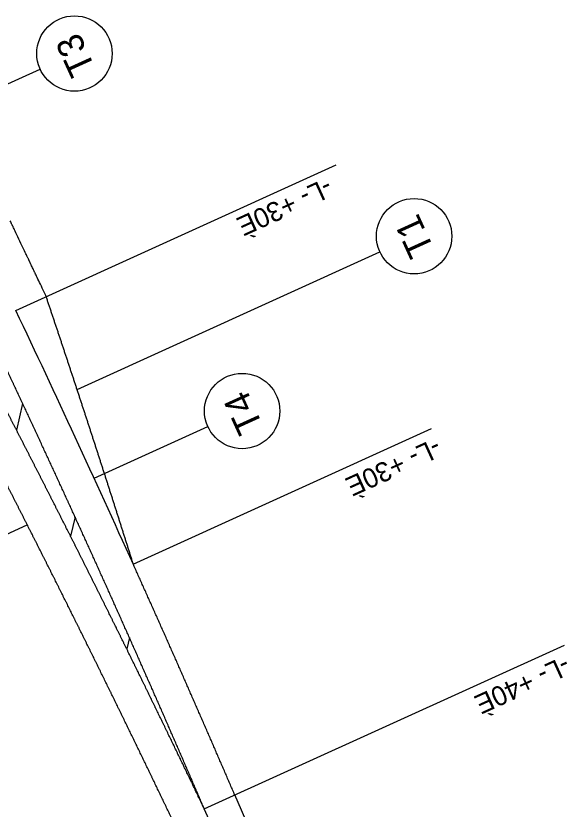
# Model space of a CAD drawing. Extents: x 1657109 to 2100937, y 684916 to 883211.
# Drawn here: x 2097963.2 to 2098160.7, y 685227.5 to 685511.8 of the extents above; entities that cross this region are included whole.
import ezdxf

# ---------------------------------------------------------------- set-up
doc = ezdxf.new("R2010")
doc.units = 0
for name, color, linetype in [('Old_Level_12', 7, 'Continuous'), ('Prop CMT Pvmt Gravel', 7, 'Continuous'), ('Prop Conc 2ft 6in Curb and Gutter', 7, 'Continuous'), ('Prop Guardrail Anchor Unit CELL', 7, 'Continuous'), ('Scratch_Level_1', 7, 'Continuous')]:
    doc.layers.add(name, color=color, linetype=linetype)

msp = doc.modelspace()

# ---------------------------------------------------------------- linework, layer by layer
at = {"layer": 'Old_Level_12'}
for p, q in [((2097965.58, 685372.9), (2097963.4, 685363.32)), ((2097984.37, 685332.2), (2097982.79, 685325.24)), ((2098003.84, 685289), (2098002.9, 685284.87))]:
    msp.add_line(p, q, dxfattribs=at)
at = {"layer": 'Prop CMT Pvmt Gravel'}
for p, q in [((2097931.15, 685474.17), (2097971.87, 685492.7)), ((2097963.18, 685406.16), (2098077.9, 685458.36)), ((2097985.12, 685377.86), (2098093.59, 685427.22)), ((2097991.24, 685346.03), (2098031.96, 685364.56)), ((2098005.22, 685315.27), (2098112.1, 685363.91)), ((2097887.48, 685292.79), (2097967.26, 685329.36)), ((2098030.69, 685227.56), (2098159.71, 685286.27))]:
    msp.add_line(p, q, dxfattribs=at)
for centre in [(2097984.16, 685498.29), (2098105.88, 685432.81), (2098044.25, 685370.15)]:
    msp.add_circle(centre, 13.5, dxfattribs=at)
at = {"layer": 'Prop Conc 2ft 6in Curb and Gutter'}
msp.add_arc((2093433.96, 683256.07), 5013.66, 24.24805, 25.39445, dxfattribs=at)
at = {"layer": 'Prop Guardrail Anchor Unit CELL'}
msp.add_line((2098097.63, 685104.2), (2098041.61, 685232.53), dxfattribs=at)
msp.add_open_spline([(2097973.92, 685411.52), (2097973.6, 685412.19), (2097972.63, 685414.24), (2097971.32, 685416.98), (2097970.33, 685419.06), (2097969.84, 685420.1), (2097969.67, 685420.44), (2097969.34, 685421.13), (2097969.01, 685421.83), (2097968.64, 685422.6), (2097968.43, 685423.06), (2097968.37, 685423.16), (2097968.35, 685423.21), (2097968.34, 685423.23), (2097968.31, 685423.29), (2097968.21, 685423.51), (2097968.11, 685423.72), (2097967.94, 685424.07), (2097967.86, 685424.24), (2097967.7, 685424.59), (2097967.61, 685424.76), (2097967.37, 685425.27), (2097967.2, 685425.62), (2097966.38, 685427.34), (2097965.07, 685430.1), (2097963.43, 685433.55), (2097962.41, 685435.7), (2097962.04, 685436.48), (2097961.96, 685436.65), (2097961.92, 685436.74), (2097961.8, 685437), (2097961.55, 685437.51), (2097961.31, 685438.03), (2097961.14, 685438.38)], degree=3, dxfattribs=at)
for points in [[(2097989.86, 685363.37), (2097989.65, 685364.02), (2097989.44, 685364.67), (2097989.22, 685365.32), (2097989.01, 685365.97), (2097988.8, 685366.62), (2097988.59, 685367.28), (2097988.37, 685367.93), (2097988.16, 685368.58), (2097987.95, 685369.23), (2097987.74, 685369.88), (2097987.52, 685370.53), (2097987.31, 685371.18), (2097987.1, 685371.83), (2097986.88, 685372.49), (2097986.67, 685373.14), (2097986.46, 685373.79), (2097986.24, 685374.44), (2097986.03, 685375.09), (2097985.82, 685375.74), (2097985.6, 685376.39), (2097985.39, 685377.04), (2097985.17, 685377.69), (2097984.96, 685378.35), (2097984.75, 685379), (2097984.53, 685379.65), (2097984.32, 685380.3), (2097984.1, 685380.95), (2097983.89, 685381.6), (2097983.67, 685382.25), (2097983.46, 685382.9), (2097983.24, 685383.55), (2097983.03, 685384.2), (2097982.81, 685384.85), (2097982.6, 685385.51), (2097982.38, 685386.16), (2097982.17, 685386.81), (2097981.95, 685387.46), (2097981.74, 685388.11), (2097981.52, 685388.76), (2097981.31, 685389.41), (2097981.09, 685390.06), (2097980.88, 685390.71), (2097980.66, 685391.36), (2097980.44, 685392.01), (2097980.23, 685392.66), (2097980.01, 685393.31), (2097979.79, 685393.96), (2097979.58, 685394.62), (2097979.36, 685395.27), (2097979.14, 685395.92), (2097978.93, 685396.57), (2097978.71, 685397.22), (2097978.49, 685397.87), (2097978.28, 685398.52), (2097978.06, 685399.17), (2097977.84, 685399.82), (2097977.63, 685400.47), (2097977.41, 685401.12), (2097977.19, 685401.77), (2097976.97, 685402.42), (2097976.76, 685403.07), (2097976.54, 685403.72), (2097976.32, 685404.37), (2097976.1, 685405.02), (2097975.88, 685405.67), (2097975.67, 685406.32), (2097975.45, 685406.97), (2097975.23, 685407.62), (2097975.01, 685408.27), (2097974.79, 685408.92), (2097974.57, 685409.57), (2097974.36, 685410.22), (2097973.92, 685411.52)], [(2098005.29, 685315.12), (2098005.09, 685315.77), (2098004.88, 685316.42), (2098004.67, 685317.07), (2098004.47, 685317.73), (2098004.26, 685318.38), (2098004.06, 685319.03), (2098003.85, 685319.68), (2098003.65, 685320.34), (2098003.44, 685320.99), (2098003.24, 685321.64), (2098003.03, 685322.29), (2098002.82, 685322.95), (2098002.62, 685323.6), (2098002.41, 685324.25), (2098002.2, 685324.9), (2098002, 685325.56), (2098001.79, 685326.21), (2098001.58, 685326.86), (2098001.38, 685327.51), (2098001.17, 685328.17), (2098000.96, 685328.82), (2098000.76, 685329.47), (2098000.55, 685330.12), (2098000.34, 685330.78), (2098000.14, 685331.43), (2097999.93, 685332.08), (2097999.72, 685332.73), (2097999.51, 685333.38), (2097999.3, 685334.04), (2097999.1, 685334.69), (2097998.89, 685335.34), (2097998.68, 685335.99), (2097998.47, 685336.65), (2097998.26, 685337.3), (2097998.06, 685337.95), (2097997.85, 685338.6), (2097997.64, 685339.25), (2097997.43, 685339.91), (2097997.22, 685340.56), (2097997.01, 685341.21), (2097996.8, 685341.86), (2097996.6, 685342.51), (2097996.39, 685343.17), (2097996.18, 685343.82), (2097995.97, 685344.47), (2097995.76, 685345.12), (2097995.55, 685345.77), (2097995.34, 685346.42), (2097995.13, 685347.08), (2097994.92, 685347.73), (2097994.71, 685348.38), (2097994.5, 685349.03), (2097994.29, 685349.68), (2097994.08, 685350.34), (2097993.87, 685350.99), (2097993.66, 685351.64), (2097993.45, 685352.29), (2097993.24, 685352.94), (2097993.03, 685353.59), (2097992.82, 685354.25), (2097992.61, 685354.9), (2097992.4, 685355.55), (2097992.19, 685356.2), (2097991.98, 685356.85), (2097991.76, 685357.5), (2097991.55, 685358.16), (2097991.34, 685358.81), (2097991.13, 685359.46), (2097990.92, 685360.11), (2097990.71, 685360.76), (2097990.5, 685361.41), (2097990.28, 685362.06), (2097990.07, 685362.72), (2097989.86, 685363.37)], [(2097987.77, 685288.41), (2097987.33, 685289.29), (2097986.9, 685290.18), (2097986.46, 685291.06), (2097986.02, 685291.95), (2097985.58, 685292.84), (2097985.14, 685293.72), (2097984.7, 685294.61), (2097984.26, 685295.49), (2097983.82, 685296.38), (2097983.38, 685297.26), (2097982.94, 685298.15), (2097982.5, 685299.03), (2097982.06, 685299.92), (2097981.62, 685300.8), (2097981.18, 685301.69), (2097980.73, 685302.57), (2097980.29, 685303.45), (2097979.85, 685304.34), (2097979.41, 685305.22), (2097978.97, 685306.11), (2097978.53, 685306.99), (2097978.08, 685307.88), (2097977.64, 685308.76), (2097977.2, 685309.64), (2097976.76, 685310.53), (2097976.31, 685311.41), (2097975.87, 685312.29), (2097975.43, 685313.18), (2097974.98, 685314.06), (2097974.54, 685314.94), (2097974.1, 685315.83), (2097973.65, 685316.71), (2097973.21, 685317.59), (2097972.76, 685318.48), (2097972.32, 685319.36), (2097971.87, 685320.24), (2097971.43, 685321.12), (2097970.98, 685322.01), (2097970.54, 685322.89), (2097970.09, 685323.77), (2097969.65, 685324.65), (2097969.2, 685325.54), (2097968.76, 685326.42), (2097968.31, 685327.3), (2097967.86, 685328.18), (2097967.42, 685329.06), (2097966.97, 685329.94), (2097966.52, 685330.83), (2097966.08, 685331.71), (2097965.63, 685332.59), (2097965.18, 685333.47), (2097964.74, 685334.35), (2097964.29, 685335.23), (2097963.84, 685336.11), (2097963.39, 685336.99), (2097962.94, 685337.88), (2097962.5, 685338.76), (2097962.05, 685339.64), (2097961.6, 685340.52), (2097961.15, 685341.4), (2097960.7, 685342.28), (2097960.25, 685343.16), (2097959.8, 685344.04), (2097959.35, 685344.92), (2097958.9, 685345.8), (2097958.45, 685346.68), (2097958, 685347.56), (2097957.55, 685348.44), (2097957.1, 685349.32), (2097956.65, 685350.2), (2097956.2, 685351.08), (2097955.75, 685351.96), (2097955.3, 685352.84), (2097954.85, 685353.72)], [(2098012.13, 685299.86), (2098011.72, 685300.77), (2098011.32, 685301.68), (2098010.91, 685302.59), (2098010.51, 685303.49), (2098010.1, 685304.4), (2098009.7, 685305.31), (2098009.29, 685306.22), (2098008.88, 685307.12), (2098008.48, 685308.03), (2098008.07, 685308.94), (2098007.66, 685309.84), (2098007.26, 685310.75), (2098006.85, 685311.66), (2098006.44, 685312.56), (2098006.03, 685313.47), (2098005.62, 685314.38), (2098005.29, 685315.12)], [(2098041.61, 685232.53), (2098041.22, 685233.44), (2098040.83, 685234.35), (2098040.43, 685235.26), (2098040.04, 685236.17), (2098039.65, 685237.08), (2098039.26, 685237.99), (2098038.86, 685238.9), (2098038.47, 685239.81), (2098038.08, 685240.72), (2098037.69, 685241.63), (2098037.29, 685242.54), (2098036.9, 685243.45), (2098036.5, 685244.36), (2098036.11, 685245.28), (2098035.72, 685246.19), (2098035.32, 685247.1), (2098034.93, 685248.01), (2098034.53, 685248.92), (2098034.14, 685249.84), (2098033.74, 685250.75), (2098033.35, 685251.66), (2098032.95, 685252.57), (2098032.56, 685253.48), (2098032.16, 685254.39), (2098031.76, 685255.3), (2098031.37, 685256.22), (2098030.97, 685257.13), (2098030.57, 685258.04), (2098030.18, 685258.95), (2098029.78, 685259.86), (2098029.38, 685260.77), (2098028.99, 685261.68), (2098028.59, 685262.59), (2098028.19, 685263.5), (2098027.79, 685264.41), (2098027.39, 685265.32), (2098027, 685266.23), (2098026.6, 685267.14), (2098026.2, 685268.05), (2098025.8, 685268.96), (2098025.4, 685269.87), (2098025, 685270.78), (2098024.6, 685271.69), (2098024.2, 685272.6), (2098023.8, 685273.51), (2098023.4, 685274.42), (2098023, 685275.33), (2098022.6, 685276.24), (2098022.2, 685277.15), (2098021.8, 685278.06), (2098021.4, 685278.97), (2098021, 685279.88), (2098020.6, 685280.79), (2098020.2, 685281.7), (2098019.79, 685282.61), (2098019.39, 685283.52), (2098018.99, 685284.43), (2098018.59, 685285.33), (2098018.19, 685286.24), (2098017.78, 685287.15), (2098017.38, 685288.06), (2098016.98, 685288.97), (2098016.58, 685289.88), (2098016.17, 685290.79), (2098015.77, 685291.69), (2098015.37, 685292.6), (2098014.96, 685293.51), (2098014.56, 685294.42), (2098014.15, 685295.33), (2098013.75, 685296.23), (2098013.34, 685297.14), (2098012.94, 685298.05), (2098012.53, 685298.96), (2098012.13, 685299.86)], [(2098019.77, 685222.59), (2098019.34, 685223.48), (2098018.91, 685224.37), (2098018.48, 685225.27), (2098018.05, 685226.16), (2098017.62, 685227.05), (2098017.2, 685227.95), (2098016.77, 685228.84), (2098016.34, 685229.74), (2098015.91, 685230.63), (2098015.48, 685231.52), (2098015.06, 685232.42), (2098014.63, 685233.31), (2098014.2, 685234.2), (2098013.77, 685235.09), (2098013.34, 685235.98), (2098012.92, 685236.87), (2098012.49, 685237.76), (2098012.06, 685238.65), (2098011.63, 685239.55), (2098011.2, 685240.44), (2098010.77, 685241.33), (2098010.34, 685242.22), (2098009.91, 685243.11), (2098009.48, 685244), (2098009.05, 685244.89), (2098008.62, 685245.78), (2098008.19, 685246.67), (2098007.76, 685247.56), (2098007.33, 685248.45), (2098006.9, 685249.34), (2098006.47, 685250.23), (2098006.04, 685251.12), (2098005.61, 685252.01), (2098005.18, 685252.9), (2098004.74, 685253.79), (2098004.31, 685254.68), (2098003.88, 685255.57), (2098003.45, 685256.46), (2098003.02, 685257.34), (2098002.58, 685258.23), (2098002.15, 685259.12), (2098001.72, 685260.01), (2098001.28, 685260.9), (2098000.85, 685261.79), (2098000.42, 685262.68), (2097999.98, 685263.57), (2097999.55, 685264.45), (2097999.12, 685265.34), (2097998.68, 685266.23), (2097998.25, 685267.12), (2097997.81, 685268.01), (2097997.38, 685268.89), (2097996.94, 685269.78), (2097996.51, 685270.67), (2097996.07, 685271.56), (2097995.64, 685272.45), (2097995.2, 685273.33), (2097994.77, 685274.22), (2097994.33, 685275.11), (2097993.9, 685276), (2097993.46, 685276.88), (2097993.02, 685277.77), (2097992.59, 685278.66), (2097992.15, 685279.54), (2097991.71, 685280.43), (2097991.28, 685281.32), (2097990.84, 685282.2), (2097990.4, 685283.09), (2097989.96, 685283.98), (2097989.53, 685284.86), (2097989.09, 685285.75), (2097988.65, 685286.63), (2097988.21, 685287.52), (2097987.77, 685288.41)]]:
    msp.add_spline(points, degree=3, dxfattribs=at)
at = {"layer": 'Scratch_Level_1'}
msp.add_line((2098088.67, 685100.13), (2098030.69, 685227.56), dxfattribs=at)
for points in [[(2097970.87, 685361.54), (2097970.45, 685362.44), (2097970.04, 685363.34), (2097969.62, 685364.24), (2097969.2, 685365.14), (2097968.78, 685366.04), (2097968.36, 685366.94), (2097967.94, 685367.84), (2097967.53, 685368.74), (2097967.11, 685369.64), (2097966.69, 685370.53), (2097966.27, 685371.43), (2097965.85, 685372.33), (2097965.43, 685373.23), (2097965.01, 685374.13), (2097964.59, 685375.03), (2097964.17, 685375.93), (2097963.75, 685376.82), (2097963.33, 685377.72), (2097962.91, 685378.62), (2097962.49, 685379.52), (2097962.06, 685380.42), (2097961.64, 685381.31), (2097961.22, 685382.21), (2097960.8, 685383.11), (2097960.38, 685384.01), (2097959.96, 685384.91), (2097959.53, 685385.8), (2097959.11, 685386.7), (2097958.69, 685387.6), (2097958.27, 685388.49), (2097957.84, 685389.39), (2097957.42, 685390.29), (2097957, 685391.19), (2097956.57, 685392.08), (2097956.15, 685392.98), (2097955.72, 685393.88), (2097955.3, 685394.77), (2097954.88, 685395.67), (2097954.45, 685396.57), (2097954.03, 685397.46), (2097953.6, 685398.36), (2097953.18, 685399.26), (2097952.75, 685400.15), (2097952.33, 685401.05), (2097951.9, 685401.94), (2097951.48, 685402.84), (2097951.05, 685403.74), (2097950.62, 685404.63), (2097950.2, 685405.53), (2097949.77, 685406.42), (2097949.35, 685407.32), (2097948.92, 685408.21), (2097948.49, 685409.11), (2097948.06, 685410), (2097947.64, 685410.9), (2097947.21, 685411.8), (2097946.78, 685412.69), (2097946.36, 685413.58), (2097945.93, 685414.48), (2097945.5, 685415.37), (2097945.08, 685416.26), (2097944.65, 685417.16), (2097944.23, 685418.05), (2097943.8, 685418.95), (2097943.37, 685419.84), (2097942.95, 685420.74), (2097942.52, 685421.63), (2097942.1, 685422.53), (2097941.67, 685423.42), (2097941.25, 685424.31), (2097940.83, 685425.21), (2097940.4, 685426.1), (2097939.98, 685427), (2097939.55, 685427.89)], [(2097965.63, 685358.98), (2097965.18, 685359.86), (2097964.72, 685360.74), (2097964.27, 685361.63), (2097963.82, 685362.51), (2097963.37, 685363.39), (2097962.91, 685364.27), (2097962.46, 685365.15), (2097962, 685366.03), (2097961.55, 685366.91), (2097961.1, 685367.79), (2097960.64, 685368.67), (2097960.19, 685369.55), (2097959.73, 685370.43), (2097959.28, 685371.31), (2097958.82, 685372.19), (2097958.37, 685373.07), (2097957.91, 685373.95), (2097957.46, 685374.83), (2097957, 685375.71), (2097956.55, 685376.59), (2097956.09, 685377.47), (2097955.63, 685378.35), (2097955.18, 685379.23), (2097954.72, 685380.11), (2097954.27, 685380.98), (2097953.81, 685381.86), (2097953.35, 685382.74), (2097952.89, 685383.62), (2097952.44, 685384.5), (2097951.98, 685385.38), (2097951.52, 685386.26), (2097951.06, 685387.13), (2097950.61, 685388.01), (2097950.15, 685388.89), (2097949.69, 685389.77), (2097949.23, 685390.65), (2097948.77, 685391.53), (2097948.31, 685392.4), (2097947.85, 685393.28), (2097947.4, 685394.16), (2097946.94, 685395.04), (2097946.48, 685395.91), (2097946.02, 685396.79), (2097945.56, 685397.67), (2097945.1, 685398.54), (2097944.64, 685399.42), (2097944.18, 685400.3), (2097943.72, 685401.18), (2097943.25, 685402.05), (2097942.79, 685402.93), (2097942.33, 685403.81), (2097941.87, 685404.68), (2097941.41, 685405.56), (2097940.95, 685406.43), (2097940.49, 685407.31), (2097940.02, 685408.19), (2097939.56, 685409.06), (2097939.1, 685409.94), (2097938.64, 685410.82), (2097938.17, 685411.7), (2097937.71, 685412.57), (2097937.25, 685413.45), (2097936.79, 685414.33), (2097936.33, 685415.21), (2097935.87, 685416.09), (2097935.4, 685416.96), (2097934.94, 685417.84), (2097934.48, 685418.72), (2097934.02, 685419.6), (2097933.56, 685420.48), (2097933.1, 685421.36), (2097932.64, 685422.24), (2097932.18, 685423.11), (2097931.72, 685423.99)], [(2098001.27, 685294.76), (2098000.87, 685295.66), (2098000.46, 685296.57), (2098000.06, 685297.47), (2097999.65, 685298.38), (2097999.25, 685299.28), (2097998.84, 685300.19), (2097998.44, 685301.09), (2097998.03, 685302), (2097997.63, 685302.9), (2097997.22, 685303.81), (2097996.81, 685304.71), (2097996.41, 685305.62), (2097996, 685306.52), (2097995.6, 685307.42), (2097995.19, 685308.33), (2097994.78, 685309.23), (2097994.37, 685310.14), (2097993.97, 685311.04), (2097993.56, 685311.94), (2097993.15, 685312.85), (2097992.74, 685313.75), (2097992.34, 685314.66), (2097991.93, 685315.56), (2097991.52, 685316.46), (2097991.11, 685317.37), (2097990.7, 685318.27), (2097990.29, 685319.17), (2097989.88, 685320.08), (2097989.48, 685320.98), (2097989.07, 685321.88), (2097988.66, 685322.79), (2097988.25, 685323.69), (2097987.84, 685324.59), (2097987.43, 685325.49), (2097987.02, 685326.4), (2097986.61, 685327.3), (2097986.19, 685328.2), (2097985.78, 685329.11), (2097985.37, 685330.01), (2097984.96, 685330.91), (2097984.55, 685331.81), (2097984.14, 685332.71), (2097983.73, 685333.62), (2097983.31, 685334.52), (2097982.9, 685335.42), (2097982.49, 685336.32), (2097982.08, 685337.22), (2097981.66, 685338.13), (2097981.25, 685339.03), (2097980.84, 685339.93), (2097980.43, 685340.83), (2097980.01, 685341.73), (2097979.6, 685342.63), (2097979.18, 685343.53), (2097978.77, 685344.44), (2097978.36, 685345.34), (2097977.94, 685346.24), (2097977.53, 685347.14), (2097977.11, 685348.04), (2097976.7, 685348.94), (2097976.28, 685349.84), (2097975.87, 685350.74), (2097975.45, 685351.64), (2097975.04, 685352.54), (2097974.62, 685353.44), (2097974.21, 685354.34), (2097973.79, 685355.24), (2097973.37, 685356.14), (2097972.96, 685357.04), (2097972.54, 685357.94), (2097972.12, 685358.84), (2097971.71, 685359.74), (2097971.29, 685360.64), (2097970.87, 685361.54)], [(2097998.63, 685293.51), (2097998.19, 685294.4), (2097997.75, 685295.29), (2097997.31, 685296.18), (2097996.87, 685297.07), (2097996.43, 685297.95), (2097995.99, 685298.84), (2097995.55, 685299.73), (2097995.11, 685300.62), (2097994.67, 685301.5), (2097994.23, 685302.39), (2097993.79, 685303.28), (2097993.34, 685304.17), (2097992.9, 685305.05), (2097992.46, 685305.94), (2097992.02, 685306.83), (2097991.58, 685307.71), (2097991.13, 685308.6), (2097990.69, 685309.49), (2097990.25, 685310.37), (2097989.81, 685311.26), (2097989.36, 685312.14), (2097988.92, 685313.03), (2097988.48, 685313.92), (2097988.03, 685314.8), (2097987.59, 685315.69), (2097987.14, 685316.57), (2097986.7, 685317.46), (2097986.26, 685318.35), (2097985.81, 685319.23), (2097985.37, 685320.12), (2097984.92, 685321), (2097984.48, 685321.89), (2097984.03, 685322.77), (2097983.59, 685323.66), (2097983.14, 685324.54), (2097982.7, 685325.43), (2097982.25, 685326.31), (2097981.8, 685327.2), (2097981.36, 685328.08), (2097980.91, 685328.97), (2097980.46, 685329.85), (2097980.02, 685330.73), (2097979.57, 685331.62), (2097979.12, 685332.5), (2097978.68, 685333.39), (2097978.23, 685334.27), (2097977.78, 685335.15), (2097977.33, 685336.04), (2097976.89, 685336.92), (2097976.44, 685337.8), (2097975.99, 685338.69), (2097975.54, 685339.57), (2097975.09, 685340.45), (2097974.64, 685341.34), (2097974.19, 685342.22), (2097973.74, 685343.1), (2097973.3, 685343.99), (2097972.85, 685344.87), (2097972.4, 685345.75), (2097971.95, 685346.64), (2097971.5, 685347.52), (2097971.05, 685348.4), (2097970.6, 685349.28), (2097970.14, 685350.16), (2097969.69, 685351.05), (2097969.24, 685351.93), (2097968.79, 685352.81), (2097968.34, 685353.69), (2097967.89, 685354.57), (2097967.44, 685355.46), (2097966.99, 685356.34), (2097966.53, 685357.22), (2097966.08, 685358.1), (2097965.63, 685358.98)], [(2098030.69, 685227.56), (2098030.3, 685228.47), (2098029.9, 685229.38), (2098029.51, 685230.29), (2098029.12, 685231.2), (2098028.73, 685232.11), (2098028.33, 685233.02), (2098027.94, 685233.93), (2098027.55, 685234.84), (2098027.16, 685235.75), (2098026.76, 685236.66), (2098026.37, 685237.57), (2098025.98, 685238.48), (2098025.59, 685239.39), (2098025.19, 685240.3), (2098024.8, 685241.21), (2098024.41, 685242.12), (2098024.01, 685243.03), (2098023.62, 685243.94), (2098023.22, 685244.85), (2098022.83, 685245.76), (2098022.44, 685246.66), (2098022.04, 685247.57), (2098021.65, 685248.48), (2098021.25, 685249.39), (2098020.86, 685250.3), (2098020.46, 685251.21), (2098020.06, 685252.12), (2098019.67, 685253.03), (2098019.27, 685253.94), (2098018.88, 685254.85), (2098018.48, 685255.75), (2098018.08, 685256.66), (2098017.69, 685257.57), (2098017.29, 685258.48), (2098016.89, 685259.39), (2098016.5, 685260.3), (2098016.1, 685261.21), (2098015.7, 685262.11), (2098015.3, 685263.02), (2098014.91, 685263.93), (2098014.51, 685264.84), (2098014.11, 685265.75), (2098013.71, 685266.65), (2098013.31, 685267.56), (2098012.91, 685268.47), (2098012.52, 685269.38), (2098012.12, 685270.28), (2098011.72, 685271.19), (2098011.32, 685272.1), (2098010.92, 685273.01), (2098010.52, 685273.91), (2098010.12, 685274.82), (2098009.72, 685275.73), (2098009.32, 685276.63), (2098008.92, 685277.54), (2098008.52, 685278.45), (2098008.12, 685279.35), (2098007.71, 685280.26), (2098007.31, 685281.17), (2098006.91, 685282.07), (2098006.51, 685282.98), (2098006.11, 685283.89), (2098005.71, 685284.79), (2098005.3, 685285.7), (2098004.9, 685286.6), (2098004.5, 685287.51), (2098004.1, 685288.42), (2098003.69, 685289.32), (2098003.29, 685290.23), (2098002.89, 685291.13), (2098002.48, 685292.04), (2098002.08, 685292.95), (2098001.68, 685293.85), (2098001.27, 685294.76)], [(2098030.69, 685227.56), (2098030.26, 685228.45), (2098029.83, 685229.34), (2098029.4, 685230.24), (2098028.98, 685231.13), (2098028.55, 685232.02), (2098028.12, 685232.92), (2098027.69, 685233.81), (2098027.26, 685234.71), (2098026.83, 685235.6), (2098026.41, 685236.49), (2098025.98, 685237.39), (2098025.55, 685238.28), (2098025.12, 685239.17), (2098024.69, 685240.07), (2098024.26, 685240.96), (2098023.83, 685241.86), (2098023.4, 685242.75), (2098022.97, 685243.64), (2098022.54, 685244.53), (2098022.11, 685245.43), (2098021.68, 685246.32), (2098021.25, 685247.21), (2098020.82, 685248.11), (2098020.39, 685249), (2098019.96, 685249.89), (2098019.53, 685250.78), (2098019.1, 685251.68), (2098018.67, 685252.57), (2098018.23, 685253.46), (2098017.8, 685254.35), (2098017.37, 685255.24), (2098016.94, 685256.14), (2098016.51, 685257.03), (2098016.07, 685257.92), (2098015.64, 685258.81), (2098015.21, 685259.7), (2098014.78, 685260.59), (2098014.34, 685261.49), (2098013.91, 685262.38), (2098013.48, 685263.27), (2098013.04, 685264.16), (2098012.61, 685265.05), (2098012.17, 685265.94), (2098011.74, 685266.83), (2098011.31, 685267.72), (2098010.87, 685268.61), (2098010.44, 685269.5), (2098010, 685270.39), (2098009.57, 685271.28), (2098009.13, 685272.18), (2098008.7, 685273.07), (2098008.26, 685273.96), (2098007.82, 685274.85), (2098007.39, 685275.74), (2098006.95, 685276.63), (2098006.52, 685277.51), (2098006.08, 685278.4), (2098005.64, 685279.29), (2098005.21, 685280.18), (2098004.77, 685281.07), (2098004.33, 685281.96), (2098003.89, 685282.85), (2098003.46, 685283.74), (2098003.02, 685284.63), (2098002.58, 685285.52), (2098002.14, 685286.41), (2098001.7, 685287.3), (2098001.27, 685288.18), (2098000.83, 685289.07), (2098000.39, 685289.96), (2097999.95, 685290.85), (2097999.51, 685291.74), (2097999.07, 685292.63), (2097998.63, 685293.51)]]:
    msp.add_spline(points, degree=3, dxfattribs=at)

# ---------------------------------------------------------------- texts
at = {"layer": 'Prop CMT Pvmt Gravel'}
for s, height, rotation, p in [('T3', 9.45, 114.4674, (2097991.82, 685492.86)), ('-L- +30È', 7, 204.4674, (2098074.61, 685453.98)), ('T1', 9.45, 114.4674, (2098113.28, 685427.94)), ('T4', 9.45, 114.4674, (2098051.95, 685364.64)), ('-L- +30È', 7, 204.4674, (2098113.59, 685360.69)), ('-L- +40È', 7, 204.4674, (2098159.79, 685282.6))]:
    msp.add_text(s, height=height, rotation=rotation, dxfattribs=at).set_placement(p)

doc.saveas('drawing.dxf')
